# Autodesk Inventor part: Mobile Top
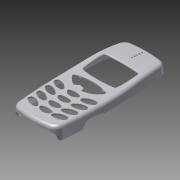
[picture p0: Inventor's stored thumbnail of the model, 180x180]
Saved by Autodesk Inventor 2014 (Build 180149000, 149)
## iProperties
Created: 2006-01
Part Number: Mobile Top
Document SubType Name: Modeling
Density: 1 g/cm^3
Material: Generic
Appearance: Default
Author: Autodesk
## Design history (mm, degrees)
sketch "Sketch1"
  geometry: L1 (-24, 54)-(24, 54); L2 (24, 54)-(24, -54); L3 (24, -54)-(-24, -54); L4 (-24, -54)-(-24, 54); A1 r 420.487 centre (396.487, -3.861) between (-20, 54) and (-21, -54); A2 r 420.487 centre (-396.487, -3.861) between (21, -54) and (20, 54); A3 r 90 centre (0, -33.75) between (20, 54) and (-20, 54); A4 r 80 centre (0, 23.195) between (-21, -54) and (21, -54); 1 further point
  constraints: 8 end point, 8 point on circle, 4 centre point, 4 point on line, 2 parallel, 2 tangent, 1 equal radius, 1 horizontal, 1 perpendicular
  dimensions: "d0" = 108 distance of L3.end L1.start; "d1" = 48 distance of L1.start L1.end; "d2" = 24 distance from line of point (0, 0) L4 (= 0.5 x d1); "d3" = 54 distance from line of point (0, 0) L1 (= 0.5 x d0); "d4" = 40 distance of A2.end A1.start; "d5" = 20 horizontal distance of point (0, 0) A1.start (= 0.5 x d4); "d6" = 42 distance of A2.start A1.end; "d7" = 90 radius of A3; "d8" = 80 radius of A4
extrude "Extrusion1" new body sketch "Sketch1" stored distance "d9" = 20; taper "d10" = 0 deg
fillet "Fillet2" dims "d70" = 8
sketch "Sketch7"
  geometry: L1 (-50.805, -3.5)-(-30.805, -3.5); L2 (-30.805, -3.5)-(-27.867, 0.545); L3 (-9.805, 0)-(56.25, 0); L4 (-56.805, -10)-(-56.805, 10) reference; L5 (56.25, -10)-(56.25, 10) reference; A1 r 8 centre (-58.802, -3.747) between (-50.805, -3.5) and (-56.805, 4); A2 r 5 centre (-23.821, -2.394) between (-23.915, 2.605) and (-27.867, 0.545); A3 r 48 centre (-23.015, -45.386) between (-10.546, 0.966) and (-23.915, 2.605); A4 r 1 centre (-10.805, 0) between (-9.805, 0) and (-10.546, 0.966)
  constraints: 8 point on circle, 6 end point, 4 centre point, 3 tangent, 1 horizontal, 1 horizontal alignment, 1 midpoint, 1 parallel, 1 point on line
  dimensions: "d51" = 20 distance of L1.start L1.end; "d52" = 8 radius of A1; "d53" = 6 distance from line of L4 L1.start; "d54" = 54 deg angle of L1 L2; "d55" = 5 distance of L1.end L2.end; "d56" = 3.5 distance between parallel lines of L1 L3; "d58" = 5 radius of A2; "d59" = 48 radius of A3; "d60" = 1 radius of A4; "d61" = 21 horizontal distance of L3.start L1.end; "d62" = 6 distance of L4.end A1.end; "d68" = 10 distance from line of L5.end L3
extrude_surface "ExtrusionSrf3" sketch "Sketch7" dims "d66" = 60, "d67" = 0
split "Split2"
fillet "Fillet1" dims "d69" = 0.5
sketch "Sketch12"
  geometry: L1 (-56.981, 8)-(-10.981, 8); L2 (-27.601, 0.545)-(-30.241, -3.088) reference; L3 (-31.05, -3.5)-(-49.773, -3.5) reference; L4 (-56.54, 2)-(-55.981, 10) reference; L5 (-55.981, 10)-(55.329, 10) reference; L6 (55.329, 10)-(56.028, 0) reference; L7 (56.028, 0)-(-8.808, 0) reference; A1 r 341.401 centre (-10.981, 349.401) between (-10.981, 8) and (19.482, 9.362); A2 r 160 centre (33.758, -150) between (56.329, 8.4) and (19.482, 9.362); A3 r 1 centre (-8.808, 1) between (-9.674, 0.5) and (-8.808, 0) reference; A4 r 1 centre (-10.54, 0) between (-9.674, 0.5) and (-10.281, 0.966) reference; A5 r 48 centre (-22.75, -45.386) between (-10.281, 0.966) and (-23.65, 2.605) reference; A6 r 5 centre (-23.556, -2.394) between (-23.65, 2.605) and (-27.601, 0.545) reference; A7 r 1 centre (-31.05, -2.5) between (-31.05, -3.5) and (-30.241, -3.088) reference; A8 r 1 centre (-49.773, -2.5) between (-50.725, -2.806) and (-49.773, -3.5) reference; A9 r 7 centre (-57.389, -4.948) between (-50.725, -2.806) and (-56.54, 2) reference
  constraints: 18 point on circle, 14 end point, 9 centre point, 4 horizontal, 3 tangent, 30 other
  dimensions: "d99" = 45 horizontal distance of L1.end L4.end; "d100" = 2 distance between parallel lines of L1 L5; "d101" = 1.6 vertical distance of L5.end A2.start; "d102" = 1 horizontal distance of L5.end A2.start; "d103" = 160 radius of A2; "d104" = 1 horizontal distance of L4.end L1.start
extrude_surface "ExtrusionSrf4" sketch "Sketch12" dims "d105" = 60, "d106" = 0
split "Split4"
fillet "Fillet7" dims "d108" = 3
feature "FaceDraft4" dims angle "d112" = 4 deg
shell "Shell3" dims "d113" = 1.5
sketch "Sketch13"
  geometry: L1 (-10.377, 0.699)-(-10.5, 0); L2 (-10.5, 0)-(10.5, 0); L3 (10.5, 0)-(10.377, 0.699); L4 (-14.135, 0)-(14.135, 0) reference; A1 r 40 centre (0, -36.707) between (8.85, 2.302) and (-8.85, 2.302); A2 r 2 centre (8.407, 0.352) between (10.377, 0.699) and (8.85, 2.302); A3 r 2 centre (-8.407, 0.352) between (-8.85, 2.302) and (-10.377, 0.699); 1 further point
  constraints: 6 end point, 6 point on circle, 4 tangent, 3 centre point, 1 collinear, 1 equal length, 1 equal radius, 1 horizontal
  dimensions: "d116" = 80 deg angle of L2 L1; "d118" = 40 radius of A1; "d569" = 2 radius of A2; "d570" = 0.6988 vertical distance of L1.start L1.end; "d571" = 21 distance of L2.end L1.end; "d572" = 10.5 distance of point (0, 0) L2.end (derived); "d573" = 0.6988 vertical distance of L2.end L3.end (derived)
extrude "Extrusion3" cut sketch "Sketch13" distance "d119" = 800; taper "d120" = 0 deg
sketch "Sketch14"
  geometry: A1 r 160 centre (0, -128.091) between (16.5, 31.056) and (-16.5, 31.056); A2 r 100 centre (0, 107.767) between (-16, 9.056) and (16, 9.056); A3 r 90 centre (73.052, 22.085) between (-16.5, 31.056) and (-16, 9.056); A4 r 90 centre (-73.052, 22.085) between (16, 9.056) and (16.5, 31.056); 3 further points
  constraints: 8 point on circle, 4 centre point, 2 horizontal alignment, 1 equal radius, 1 other
  dimensions: "d122" = 33 distance of A1.start A1.end; "d123" = 16.5 horizontal distance of point (0, 0) A1.end (derived); "d124" = 32 distance of A2.end A2.start; "d125" = 16 horizontal distance of point (0, 0) A2.start (derived); "d126" = 22 vertical distance of A2.start A1.end; "d127" = 160 radius of A1; "d128" = 100 radius of A2; "d129" = 90 radius of A3; "d130" = 25 vertical distance of A1.start point (10.5, 56.056)
extrude "Extrusion4" cut sketch "Sketch14" distance "d131" = 60; taper "d132" = 0 deg
fillet "Fillet9" dims "d133" = 2
fillet "Fillet10" dims "d134" = 1
sketch "Sketch15" dims "d138" = 22, "d139" = 20
  geometry: L1 (1, -9.972)-(0, -5.972); L2 (0, -5.972)-(-4.5, -5.172); L3 (-4.5, -5.172)-(-8, -8.163); A1 r 45 centre (0, -42) between (16.648, -0.193) and (-16.648, -0.193); 8 further points; 1 other entity
  constraints: 6 end point, 2 horizontal alignment, 2 point on circle, 2 vertical alignment, 1 centre point, 8 other
  dimensions: "d137" = 12 distance of point (0, 0) point (0, 12); "d140" = 45 radius of A1; "d141" = 42 distance of point (0, 0) A1.centre; "d164" = 1 horizontal distance of point (0, 0) L1.start; "d165" = 8 horizontal distance of point (0, 0) L3.end; "d166" = 4 vertical distance of L1.start L1.end; "d167" = 4.5 horizontal distance of L1.end L2.end; "d168" = 0.8 vertical distance of L1.end L2.end
extrude "Extrusion7" cut sketch "Sketch15" stored distance "d169" = 1.5; taper "d170" = 0 deg
fillet "Fillet12" dims "d171" = 1.2
workplane "Work Plane7"
sketch "Sketch17"
  geometry: L1 (-15.808, -1.477)-(15.808, -1.477); A1 r 18.61 centre (0.054, 8.614) between (-8, -8.163) and (1, -9.972)
  constraints: 2 end point, 2 point on circle, 1 centre point, 1 horizontal, 3 other
extrude "Extrusion8" cut sketch "Sketch17" distance "d173" = 2.5; taper "d174" = 0 deg
workplane "Work Plane8"
sketch "Sketch18" dims "d176" = 1
  geometry: A1 r 18.31 centre (-0.007, -19.291) between (1, -1.008) and (-8, -2.818); A2 r 19.31 centre (-0.007, -19.291) between (1.055, -0.01) and (-8.435, -1.917); 8 further points
  constraints: 4 point on circle, 2 centre point, 2 concentric, 2 horizontal alignment, 19 other
extrude "Extrusion9" cut sketch "Sketch18" distance "d177" = 0.5; taper "d178" = 0 deg
sketch "Sketch19"
  geometry: L1 (-1, 1.008)-(-0.189, 4.254) reference; L2 (-12.654, 12.165)-(-12.384, 11.797); L3 (-12.384, 11.797)-(-10.52, 12.182); L4 (-10.52, 12.182)-(-10.373, 12.769); A1 r 45 centre (0, -31.019) between (15.233, 11.324) and (-15.233, 11.324) reference
  constraints: 6 end point, 2 point on circle, 1 parallel
extrude "Extrusion10" join sketch "Sketch19" distance "d179" = 0.5; taper "d180" = 0 deg
mirror "Mirror1"
sketch "Sketch20"
  geometry: L1 (0, 0)-(41.879, 0) reference; A1 r 2.5 centre (3, -3) between (3.096, -0.502) and (1.347, -4.876); A2 r 12 centre (2.633, -12.493) between (11.888, -4.854) and (3.096, -0.502); A3 r 12 centre (9.281, 4.127) between (1.347, -4.876) and (10.715, -7.787); A4 r 1.8 centre (10.5, -6) between (10.715, -7.787) and (11.888, -4.854); A5 r 14 centre (20.939, -16.649) between (25.738, -3.497) and (16.141, -3.497); A6 r 1.6 centre (16.689, -5) between (16.141, -3.497) and (15.43, -5.987); A7 r 7 centre (20.939, -1.669) between (15.43, -5.987) and (26.449, -5.987); A8 r 1.6 centre (25.189, -5) between (26.449, -5.987) and (25.738, -3.497); A9 r 1.8 centre (10.818, -15) between (11.033, -16.787) and (12.206, -13.854); A10 r 12 centre (9.599, -4.873) between (1.665, -13.876) and (11.033, -16.787); A11 r 2.5 centre (3.318, -12) between (3.414, -9.502) and (1.665, -13.876); A12 r 12 centre (2.951, -21.493) between (12.206, -13.854) and (3.414, -9.502); A13 r 2.5 centre (3.831, -21) between (3.928, -18.502) and (2.178, -22.876); A14 r 12 centre (3.465, -30.493) between (12.719, -22.854) and (3.928, -18.502); A15 r 12 centre (10.113, -13.873) between (2.178, -22.876) and (11.546, -25.787); A16 r 1.8 centre (11.331, -24) between (11.546, -25.787) and (12.719, -22.854); A17 r 12 centre (37.198, -39.499) between (37.373, -27.5) and (27.95, -31.853); A18 r 2.5 centre (37.337, -30) between (39.008, -31.859) and (37.373, -27.5); A19 r 12 centre (30.987, -22.934) between (29.046, -34.776) and (39.008, -31.859); A20 r 1.8 centre (29.337, -33) between (27.95, -31.853) and (29.046, -34.776); A21 r 2.5 centre (4.542, -30) between (4.638, -27.502) and (2.889, -31.876); A22 r 12 centre (10.823, -22.873) between (2.889, -31.876) and (12.257, -34.787); A23 r 1.8 centre (12.042, -33) between (12.257, -34.787) and (13.43, -31.854); A24 r 12 centre (4.175, -39.493) between (13.43, -31.854) and (4.638, -27.502); A25 r 414.55 centre (417.426, 7.12) between (3, -3) and (4.542, -30); A26 r 417.487 centre (417.426, 7.12) between (0, 0) and (2.281, -37.041) reference; A27 r 7 centre (20.939, -28.669) between (15.43, -32.987) and (26.449, -32.987); A28 r 1.6 centre (25.189, -32) between (26.449, -32.987) and (25.738, -30.497); A29 r 14 centre (20.939, -43.649) between (25.738, -30.497) and (16.141, -30.497); A30 r 1.6 centre (16.689, -32) between (16.141, -30.497) and (15.43, -32.987); A31 r 1.6 centre (16.689, -14) between (16.141, -12.497) and (15.43, -14.987); A32 r 1.6 centre (25.189, -14) between (26.449, -14.987) and (25.738, -12.497); A33 r 7 centre (20.939, -10.669) between (15.43, -14.987) and (26.449, -14.987); A34 r 14 centre (20.939, -25.649) between (25.738, -12.497) and (16.141, -12.497); A35 r 1.6 centre (16.689, -23) between (16.141, -21.497) and (15.43, -23.987); A36 r 1.6 centre (25.189, -23) between (26.449, -23.987) and (25.738, -21.497); A37 r 7 centre (20.939, -19.669) between (15.43, -23.987) and (26.449, -23.987); A38 r 14 centre (20.939, -34.649) between (25.738, -21.497) and (16.141, -21.497); A39 r 1.8 centre (30.047, -24) between (28.66, -22.853) and (29.756, -25.776); A40 r 12 centre (37.909, -30.499) between (38.084, -18.5) and (28.66, -22.853); A41 r 12 centre (31.697, -13.934) between (29.756, -25.776) and (39.718, -22.859); A42 r 2.5 centre (38.047, -21) between (39.718, -22.859) and (38.084, -18.5); A43 r 1.8 centre (30.561, -15) between (29.174, -13.853) and (30.27, -16.776); A44 r 12 centre (32.211, -4.934) between (30.27, -16.776) and (40.232, -13.859); A45 r 12 centre (38.422, -21.499) between (38.597, -9.5) and (29.174, -13.853); A46 r 2.5 centre (38.561, -12) between (40.232, -13.859) and (38.597, -9.5); A47 r 1.8 centre (30.879, -6) between (29.491, -4.853) and (30.587, -7.776); A48 r 12 centre (32.528, 4.066) between (30.587, -7.776) and (40.55, -4.859); A49 r 12 centre (38.74, -12.499) between (38.915, -0.5) and (29.491, -4.853); A50 r 2.5 centre (38.879, -3) between (40.55, -4.859) and (38.915, -0.5); A51 r 414.55 centre (-375.547, 7.12) between (37.337, -30) and (38.879, -3); A52 r 417.487 centre (-375.547, 7.12) between (39.597, -37.041) and (41.879, 0) reference; 1 further point
  constraints: 104 point on circle, 50 centre point, 48 tangent, 9 vertical alignment, 7 horizontal alignment, 4 equal radius, 2 coincident, 2 concentric
  dimensions: "d181" = 12 radius of A2; "d182" = 12 radius of A3 (derived); "d183" = 2.5 radius of A1; "d184" = 1.8 radius of A4; "d185" = 7.5 horizontal distance of A4.centre A1.centre; "d186" = 3 vertical distance of A4.centre A1.centre; "d187" = 8.5 distance of A8.centre A6.centre; "d188" = 1.6 radius of A6; "d189" = 14 radius of A5; "d190" = 7 radius of A7; "d193" = 12 radius of A12; "d194" = 12 radius of A10 (derived); "d195" = 2.5 radius of A11; "d196" = 1.8 radius of A9; "d197" = 7.5 horizontal distance of A9.centre A11.centre (derived); "d198" = 3 vertical distance of A9.centre A11.centre (derived); "d199" = 12 radius of A14; "d200" = 12 radius of A15 (derived); "d201" = 2.5 radius of A13; "d202" = 1.8 radius of A16; "d203" = 7.5 horizontal distance of A16.centre A13.centre (derived); "d204" = 3 vertical distance of A16.centre A13.centre (derived); "d205" = 8 horizontal distance of A18.centre A20.centre; "d206" = 3 vertical distance of A18.centre A20.centre; "d207" = 1.8 radius of A20; "d208" = 12 radius of A17; "d209" = 12 radius of A19; "d210" = 2.5 radius of A18; "d211" = 12 radius of A24; "d212" = 12 radius of A22 (derived); "d213" = 2.5 radius of A21; "d214" = 1.8 radius of A23; "d215" = 7.5 horizontal distance of A23.centre A21.centre (derived); "d216" = 3 vertical distance of A23.centre A21.centre (derived); "d217" = 3 distance from line of L1 A1.centre; "d218" = 9 vertical distance of A9.centre A4.centre; "d219" = 9 vertical distance of A16.centre A9.centre; "d220" = 9 vertical distance of A23.centre A16.centre; "d222" = 3 horizontal distance of L1.start A1.centre; "d223" = 8.5 distance of A28.centre A30.centre (derived); "d224" = 1.6 radius of A30 (derived); "d225" = 14 radius of A29 (derived); "d226" = 7 radius of A27 (derived); "d227" = 8.5 distance of A32.centre A31.centre (derived); "d228" = 1.6 radius of A31 (derived); "d229" = 14 radius of A34 (derived); "d230" = 7 radius of A33 (derived); "d231" = 8.5 distance of A36.centre A35.centre (derived); "d232" = 1.6 radius of A35 (derived); "d233" = 14 radius of A38 (derived); "d234" = 7 radius of A37 (derived); "d235" = 9 distance of A32.centre A8.centre; "d236" = 9 distance of A36.centre A32.centre (derived); "d237" = 9 distance of A28.centre A36.centre (derived); "d238" = 5 distance from line of L1 A6.centre; "d239" = 8 horizontal distance of A42.centre A39.centre; "d240" = 3 vertical distance of A42.centre A39.centre; "d241" = 1.8 radius of A39; "d242" = 12 radius of A40; "d243" = 12 radius of A41; "d244" = 2.5 radius of A42; "d245" = 8 horizontal distance of A46.centre A43.centre; "d246" = 3 vertical distance of A46.centre A43.centre; "d247" = 1.8 radius of A43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
extrude "Extrusion12" cut sketch "Sketch20" stored distance "d259" = 10; taper "d260" = 0 deg
sketch "Sketch21"
  geometry: L1 (52.823, 8.86)-(53.02, 11.352); L2 (53.02, 11.352)-(40.06, 12.376); L3 (40.06, 12.376)-(39.863, 9.883); L4 (-68.28, 0)-(91.232, 0) reference; A1 r 158.5 centre (33.758, -150) between (53.437, 7.274) and (32.867, 8.497) reference; A2 r 160 centre (33.758, -150) between (53.623, 8.762) and (33.868, 10) reference; A3 r 90 centre (53.409, 98.858) between (39.863, 9.883) and (52.823, 8.86)
  constraints: 8 point on circle, 6 end point, 3 centre point, 2 perpendicular, 1 parallel, 8 other
  dimensions: "d261" = 90 radius of A3; "d262" = 13 distance of L1.end L2.end; "d264" = 2.5 distance of L1.start L1.end; "d266" = 0.8 horizontal distance of A2.start L1.start
revolve "Revolution1" sketch "Sketch21" stored, may be unused: angle "d265" = 90 deg
sketch "Sketch22"
  geometry: L1 (39.983, 8.378)-(51.947, 7.453); L2 (39.983, 8.378)-(39.998, 8.577); L3 (39.998, 8.577)-(51.945, 7.654); L4 (51.945, 7.654)-(51.947, 7.453); A1 r 158.5 centre (33.758, -150) between (53.437, 7.274) and (31.867, 8.489) reference
  constraints: 8 end point, 4 point on circle, 1 centre point, 1 parallel, 1 perpendicular, 4 other
  dimensions: "d267" = 12 distance of L1.start L1.end; "d268" = 1.5 distance of L1.end A1.start; "d575" = 0.2 distance between parallel lines of L1 L3; "d576" = 95 deg angle of L3 L4
extrude "Extrusion13" cut sketch "Sketch22" stored distance "d270" = 10; taper "d271" = 0 deg
sketch "Sketch23"
  geometry: L1 (10, 0)-(0, 0) reference; L2 (10, -11.983)-(0, -11.983) reference; L3 (-4, 0)-(14, 0); L4 (14, 0)-(12, -11.983); L5 (12, -11.983)-(-2, -11.983); L6 (-2, -11.983)-(-4, 0); 1 further point
  constraints: 8 end point, 2 point on line, 1 equal length, 1 parallel
  dimensions: "d272" = 18 distance of L3.start L3.end; "d273" = 9 horizontal distance of point (5, -51.201) L3.start (derived); "d274" = 14 distance of L4.end L5.end; "d275" = 7 horizontal distance of point (5, -51.201) L5.end (derived)
extrude "Extrusion14" cut sketch "Sketch23" stored distance "d276" = 10; taper "d277" = 0 deg
delete_face "Delete Face2"
fillet "Fillet13" dims "d278" = 2
sketch "Sketch24" dims "d280" = 1, "d281" = 0.5, "d285" = 1, "d286" = 0.5, "d287" = 1, "d288" = 0.5, "d289" = 1, "d290" = 0.5, "d291" = 1, "d292" = 0.5
  geometry: L1 (0, -68.275)-(0, 91.177) reference; L2 (6.639, 51.93)-(-6.639, 51.93) reference; 7 further points; 5 other entities
  constraints: 5 vertical alignment, 1 point on line, 10 other
  dimensions: "d293" = 2.5 distance of point (0, 48.647) point (0, 51.147); "d294" = 2.5 distance of point (0, 46.147) point (0, 48.647) (derived); "d295" = 2.5 distance of point (0, 46.147) point (0, 43.647) (derived); "d296" = 2.5 distance of point (0, 43.647) point (0, 41.147) (derived); "d552" = 0.8 distance from line of L2 point (0, 51.147)
extrude "Extrusion44" cut sketch "Sketch24" stored distance "d553" = 10; taper "d554" = 0 deg
sketch "Sketch26" dims "d301" = 0.8, "d302" = 0.8
  geometry: L1 (47.842, -0.062)-(47.842, 0.011); L2 (0.8, 0.011)-(0.796, 0.318); L3 (0.796, 0.318)-(0.794, -1.154); L4 (47.842, -0.062)-(47.842, -1.154); L5 (13.53, 64.607)-(14.113, 64.674); L6 (14.113, 64.674)-(14.113, 65.481); L7 (14.113, 65.481)-(13.821, 65.447); L8 (35.12, 64.606)-(32.991, 64.859); L9 (32.991, 64.859)-(32.991, 65.659); L10 (32.991, 65.659)-(34.821, 65.447); L11 (1.588, -1.154)-(0.085, -1.154) reference; L12 (48.557, -1.154)-(47.053, -1.154) reference; 16 further points
  constraints: 20 end point, 2 parallel, 2 point on line, 1 collinear, 1 vertical, 38 other
  dimensions: "d303" = 0.8 distance of L8.end L9.end
extrude "Extrusion17" cut sketch "Sketch26" distance "d304" = 0.6; taper "d305" = 0 deg
fillet "Fillet15" dims "d306" = 1
sketch "Sketch25"
  geometry: L1 (5.22, 59.588)-(11.22, 59.588); L2 (11.22, 59.588)-(11.22, 63.588); L3 (43.421, 59.588)-(37.421, 59.588); L4 (37.421, 59.588)-(37.421, 63.588); 6 further points
  constraints: 8 end point, 3 perpendicular, 2 equal length, 1 horizontal, 8 other
  dimensions: "d297" = 6 distance of L1.start L1.end; "d298" = 4 distance of L1.end L2.end
extrude "Extrusion16" join sketch "Sketch25" stored distance "d299" = 6; taper "d300" = 0 deg
sketch "Sketch27" dims "d307" = 0.5, "d308" = 0.5
  geometry: L1 (5.22, 59.588)-(5.672, 59.373); L2 (11.251, 63.087)-(11.22, 63.588); L3 (37.421, 63.588)-(37.399, 63.085); L4 (43.421, 59.588)-(42.97, 59.373); 4 further points
  constraints: 8 end point, 16 other
extrude "Extrusion18" cut sketch "Sketch27" distance "d309" = 3; taper "d310" = 0 deg
sketch "Sketch28"
  geometry: L1 (11.22, 63.082)-(11.22, 59.588) reference; L2 (11.22, 59.588)-(5.779, 59.588) reference; L3 (37.421, 59.588)-(37.421, 63.082) reference; L4 (42.863, 59.588)-(37.421, 59.588) reference; L5 (11.22, 61.588)-(6.779, 59.588); L6 (37.421, 61.588)-(41.863, 59.588)
  constraints: 4 end point, 4 point on line
  dimensions: "d311" = 2 distance from line of L2 L5.start; "d312" = 1 distance of L2.end L5.end; "d313" = 1 distance of L4.start L6.end (derived); "d314" = 2 distance from line of L4 L6.start (derived)
extrude "Extrusion19" cut sketch "Sketch28" distance "d315" = 3; taper "d316" = 0 deg
sketch "Sketch29"
  geometry: L1 (11.22, 63.082)-(11.22, 61.588) reference; L2 (6.779, 59.588)-(11.22, 61.588) reference; L3 (37.421, 61.588)-(37.421, 63.082) reference; L4 (37.421, 61.588)-(41.863, 59.588) reference; L5 (10.72, 63.006)-(10.72, 61.362); L6 (37.921, 63.006)-(37.921, 61.362); 2 further points
  constraints: 4 end point, 2 parallel, 2 point on line, 4 other
  dimensions: "d317" = 0.5 distance between parallel lines of L1 L5; "d318" = 0.5 distance between parallel lines of L3 L6 (derived)
extrude "Extrusion20" cut sketch "Sketch29" distance "d319" = 3; taper "d320" = 0 deg
fillet "Fillet16" dims "d321" = 1
fillet "Fillet17" dims "d322" = 0.1
fillet "Fillet18" dims "d323" = 0.1
sketch "Sketch30"
  geometry: L1 (5.767, 0)-(0, 0) reference; L2 (0, 0)-(0, -3) reference; L3 (0.6, -0.6)-(5.167, -0.6); L4 (5.167, -0.6)-(5.167, -2.4); L5 (5.167, -2.4)-(0.6, -2.4); L6 (0.6, -2.4)-(0.6, -0.6); L7 (2.4, -0.6)-(2.4, -2.4); L8 (3, -0.6)-(3, -2.4); L9 (-31.368, -0.6)-(-26.801, -0.6); L10 (-26.801, -0.6)-(-26.801, -2.4); L11 (-26.801, -2.4)-(-31.368, -2.4); L12 (-31.368, -2.4)-(-31.368, -0.6); L13 (-29.201, -0.6)-(-29.201, -2.4); L14 (-28.601, -0.6)-(-28.601, -2.4); L15 (-26.201, 0)-(-26.201, -3) reference; L16 (-26.201, 0)-(-31.968, 0) reference
  constraints: 24 end point, 8 point on line, 6 parallel, 4 perpendicular, 2 horizontal
  dimensions: "d324" = 0.6 distance between parallel lines of L15 L10 (derived); "d325" = 0.6 distance between parallel lines of L16 L9; "d326" = 0.6 distance from line of L15.end L11 (derived); "d327" = 0.6 distance from line of L16.end L12 (derived); "d328" = 0.6 distance between parallel lines of L14 L13 (derived); "d329" = 1.8 distance between parallel lines of L10 L14; "d330" = 0.6 distance between parallel lines of L1 L3 (derived); "d331" = 0.6 distance between parallel lines of L2 L6 (derived); "d332" = 0.6 distance from line of L1.start L4 (derived); "d333" = 0.6 distance from line of L2.end L5 (derived); "d334" = 0.6 distance between parallel lines of L8 L7 (derived); "d335" = 1.8 distance between parallel lines of L6 L7 (derived)
extrude "Extrusion21" cut sketch "Sketch30" distance "d336" = 2; taper "d337" = -2 deg
fillet "Fillet19" dims "d338" = 2
fillet "Fillet20" dims "d339" = 0.3
fillet "Fillet33" dims "d577" = 0.3
fillet "Fillet21" dims "d340" = 0.3
sketch "Sketch31" dims "d342" = 0.8, "d343" = 0.8 (derived), "d344" = 1, "d345" = 1
  geometry: L1 (43.35, 2.065)-(41.554, 2.197); L2 (2.055, 2.197)-(0.265, 2.006); L3 (43.023, 20.177)-(44.828, 20.177); L4 (44.828, 19.414)-(44.828, 20.177); L5 (43.023, 19.359)-(43.023, 20.177); L6 (-1.219, 20.871)-(0.587, 20.871); L7 (0.587, 19.341)-(0.587, 20.871); L8 (-1.219, 19.403)-(-1.219, 20.871); A1 r 419.585 centre (418.291, 46.474) between (-0.411, 19.274) and (1.061, 2.091) reference; A2 r 419.585 centre (-374.682, 46.474) between (42.549, 2.091) and (44.02, 19.274) reference; A3 r 420.385 centre (418.291, 46.474) between (-1.209, 19.222) and (0.265, 2.006); A4 r 420.385 centre (-374.682, 46.474) between (43.35, 2.065) and (44.818, 19.222); A5 r 418.585 centre (418.291, 46.474) between (0.587, 19.339) and (2.055, 2.197); A6 r 418.585 centre (-374.682, 46.474) between (41.554, 2.197) and (43.022, 19.339); 2 further points
  constraints: 16 end point, 8 point on circle, 5 perpendicular, 4 centre point, 4 concentric, 1 horizontal, 14 other
extrude "Extrusion22" cut sketch "Sketch31" distance "d346" = 0.8; taper "d347" = 0 deg
fillet "Fillet23" dims "d348" = 1
sketch "Sketch32"
  geometry: L1 (-40.934, 2.091)-(-41.73, 2.006) reference; L2 (1.356, 2.065)-(0.557, 2.123) reference; L3 (-40.934, 2.091)-(-38.934, 2.304); L4 (-38.934, 2.304)-(-38.934, -0.498); L5 (-41.768, -0.498)-(-40.103, -0.498) reference; L6 (-40.103, -0.498)-(-38.934, -0.498); L7 (-0.277, -0.498)-(1.388, -0.498) reference; L8 (0.557, 2.123)-(-1.443, 2.27); L9 (-1.443, 2.27)-(-1.443, -0.498); L10 (-0.277, -0.498)-(-1.443, -0.498); L11 (-41.73, 2.006)-(-40.936, -0.498); L12 (1.356, 2.065)-(0.555, -0.498)
  constraints: 16 end point, 4 collinear, 3 midpoint, 2 vertical, 1 point on line
  dimensions: "d349" = 2 horizontal distance of L3.end L1.start; "d350" = 2 horizontal distance of L2.end L8.end (derived)
extrude "Extrusion23" join sketch "Sketch32" stored distance "d351" = 4; taper "d352" = 0 deg
sketch "Sketch33"
  geometry: L1 (-38.934, -0.498)-(-40.936, -0.498) reference; L2 (-38.934, 2.304)-(-38.934, -0.498) reference; L3 (-41.73, 2.006)-(-38.934, 2.304) reference; L4 (-40.936, -0.498)-(-41.73, 2.006) reference; L5 (-1.443, 2.27)-(1.356, 2.065) reference; L6 (-1.443, -0.498)-(-1.443, 2.27) reference; L7 (0.555, -0.498)-(-1.443, -0.498) reference; L8 (1.356, 2.065)-(0.555, -0.498) reference
extrude "Extrusion24" cut sketch "Sketch33" distance "d353" = 1; taper "d354" = 0 deg
workplane "Work Plane13"
sketch "Sketch48"
  geometry: L1 (-3.205, -4.18)-(-6.006, -4.18) reference; L2 (-3.205, -4.18)-(-3.205, -7.18) reference; L3 (-3.433, -4.18)-(-3.205, -4.18); L4 (-3.205, -5.723)-(-3.205, -4.18); A1 r 8.5 centre (4.764, -6.426) between (-0.042, 0.584) and (-3.433, -4.18); A2 r 8 centre (4.764, -6.426) between (2.768, 1.32) and (-3.232, -6.18) reference; 2 further points
  constraints: 4 end point, 3 point on circle, 2 point on line, 1 centre point, 1 collinear, 1 concentric, 1 perpendicular, 6 other
  dimensions: "d379" = 0.5 radial gap between concentric circles of A1 A2
extrude "Extrusion34" join sketch "Sketch48" stored distance "d380" = 1.5; taper "d381" = 0 deg
sketch "Sketch50"
  geometry: L1 (-2.001, 3)-(-2.001, 1.456) reference; L2 (-5.793, 7.18)-(-5.793, -1.377); L3 (-5.793, -1.377)-(-2.001, -1.377); L4 (-2.001, -1.377)-(-2.001, 1.456); A1 r 6.8 centre (-8.48, 0.933) between (-2.001, 3) and (-5.793, 7.18)
  constraints: 6 end point, 2 perpendicular, 2 point on circle, 1 centre point, 1 parallel
  dimensions: "d395" = 6.8 radius of A1
extrude "Extrusion35" cut sketch "Sketch50" stored distance "d382" = 7; taper "d383" = 0 deg
sketch "Sketch53"
  geometry: L1 (3, -0.291)-(3, 0.229) reference
sketch "3D Sketch4"
feature "LoftSrf3" sketch "Sketch53", "3D Sketch4" dims "d384" = 0, "d385" = 90 deg, "d386" = 0, "d387" = 90 deg, "d388" = 0, "d389" = 90 deg
  node "Edges2"
feature "Extend1" dims "d390" = 0.25
thicken "Thicken1" dims "d391" = 1, "d392" = 1
workplane "Work Plane15"
sketch "Sketch54"
  geometry: L1 (3.433, -4.18)-(3.205, -4.18) reference; L2 (3.205, -5.723)-(3.205, -4.18) reference; A1 r 8.5 centre (-4.764, -6.426) between (3.433, -4.18) and (0.042, 0.584) reference; A2 r 8 centre (-4.764, -6.426) between (3.232, -6.18) and (-2.768, 1.32) reference; 1 further point
  constraints: 1 other
extrude "Extrusion36" join sketch "Sketch54" stored distance "d393" = 7; taper "d394" = 0 deg
sketch "Sketch55"
  geometry: L1 (1.998, 3)-(1.998, 1.456) reference; L2 (5.793, 7.18)-(5.793, -3.94); L3 (5.793, -3.94)-(1.998, -3.526); L4 (1.998, -3.526)-(1.998, 1.456); A1 r 6.8 centre (8.476, 0.931) between (5.793, 7.18) and (1.998, 3)
  constraints: 6 end point, 2 parallel, 2 point on circle, 1 centre point
  dimensions: "d396" = 6.8 radius of A1
extrude "Extrusion37" cut sketch "Sketch55" stored distance "d397" = 7; taper "d398" = 0 deg
sketch "3D Sketch5"
feature "LoftSrf4" sketch "3D Sketch5" dims "d399" = 0, "d400" = 90 deg, "d401" = 0, "d402" = 90 deg, "d403" = 0, "d404" = 90 deg
  node "Edges3"
  node "Edges4"
feature "Extend2" dims "d405" = 0.25
thicken "Thicken2" dims "d406" = 1, "d407" = 1
sketch "Sketch56"
  geometry: L1 (-50.335, -3.5)-(-50.335, -9.751); L2 (-50.335, -9.751)-(-55.259, -9.751); L3 (-55.259, -9.751)-(-55.076, -3.044); L4 (-55.076, -3.044)-(-50.833, -3.044)
  constraints: 8 end point, 1 parallel, 1 perpendicular, 1 vertical, 1 other
extrude "Extrusion38" cut sketch "Sketch56" stored distance "d408" = 7; taper "d409" = 0 deg
fillet "Fillet24" dims "d410" = 0.5
sketch "Sketch57"
  geometry: L1 (2.5, 2.521)-(2.5, 1.289); L2 (2.5, 1.289)-(0.5, 0.72); L3 (0.5, 0.72)-(0.5, 2.521); L4 (0.5, 2.521)-(2.5, 2.521); L5 (3, 2.854)-(3, 0.789) reference; L6 (0, 0.52)-(0, 2.895) reference; L7 (0, 3.021)-(3, 3.021) reference
  constraints: 8 end point, 1 parallel, 1 perpendicular, 1 vertical
  dimensions: "d411" = 0.5 distance between parallel lines of L5 L1; "d412" = 0.5 distance between parallel lines of L4 L7 (derived); "d413" = 0.5 distance between parallel lines of L6 L3 (derived); "d414" = 0.2 vertical distance of L6.start L2.end; "d415" = 0.5 horizontal distance of L5.end L1.end
extrude "Extrusion39" cut sketch "Sketch57" distance "d416" = 1.8; taper "d417" = -2 deg
fillet "Fillet25" dims "d418" = 0.1
sketch "Sketch58"
  geometry: L1 (-3, 2.537)-(-3, 0.789) reference; L2 (0, 3.037)-(-3, 3.037) reference; L3 (-3, 0.789)-(-2, 0.789) reference; L4 (0, 0.52)-(0, 2.537) reference; L5 (-2.5, 2.537)-(-2.5, 1.289); L6 (-2.5, 1.289)-(-0.5, 0.72); L7 (-0.5, 0.72)-(-0.5, 2.537); L8 (-0.5, 2.537)-(-2.5, 2.537)
  constraints: 8 end point, 2 parallel, 1 perpendicular
  dimensions: "d419" = 0.5 distance between parallel lines of L2 L8; "d420" = 0.5 distance between parallel lines of L1 L5 (derived); "d421" = 0.5 distance between parallel lines of L4 L7 (derived); "d422" = 0.5 horizontal distance of L1.end L5.end (derived); "d423" = 0.2 vertical distance of L4.start L6.end
extrude "Extrusion40" cut sketch "Sketch58" distance "d424" = 1.8; taper "d425" = -2 deg
fillet "Fillet26" dims "d426" = 0.1
fillet "Fillet27" dims "d427" = 0.1
fillet "Fillet28" dims "d428" = 0.1
fillet "Fillet29" dims "d429" = 0.1
fillet "Fillet30" dims "d430" = 0.1
workplane "Work Plane16"
sketch "Sketch59"
  geometry: L1 (0, -4.826)-(0, -0.108) reference; L2 (0, -0.108)-(2.9, -0.108) reference; L3 (0, 27.54)-(0, 32.258) reference; L4 (0, 27.54)-(2.9, 27.54) reference; L5 (0.5, -4.326)-(2.5, -4.326); L6 (2.5, -4.326)-(2.5, -0.608); L7 (2.5, -0.608)-(0.5, -0.608); L8 (0.5, -0.608)-(0.5, -4.326); L9 (0.5, 28.04)-(2.5, 28.04); L10 (2.5, 28.04)-(2.5, 31.758); L11 (2.5, 31.758)-(0.5, 31.758); L12 (0.5, 31.758)-(0.5, 28.04)
  constraints: 16 end point, 4 parallel, 2 horizontal, 2 perpendicular, 1 collinear
  dimensions: "d431" = 0.5 distance between parallel lines of L1 L8; "d432" = 0.5 distance between parallel lines of L7 L2 (derived); "d433" = 0.5 distance between parallel lines of L3 L12 (derived); "d434" = 0.5 distance between parallel lines of L4 L9 (derived); "d435" = 2 distance of L5.start L5.end; "d436" = 0.5 distance from line of L1.start L5 (derived); "d437" = 0.5 distance from line of L3.end L11 (derived)
extrude "Extrusion41" cut sketch "Sketch59" distance "d438" = 1.8; taper "d439" = 0 deg
fillet "Fillet31" dims "d440" = 1
workplane "Work Plane17"
sketch "Sketch62" dims "d460" = 1.5
  geometry: 20 further points
  constraints: 40 other
extrude "Extrusion43" cut sketch "Sketch62" stored distance "d461" = 0.4; taper "d462" = 0 deg
body "Solid1"
body "Srf1"
body "Srf2"
body "Srf3"
body "Srf4"
other parameters: "d175" = 0
